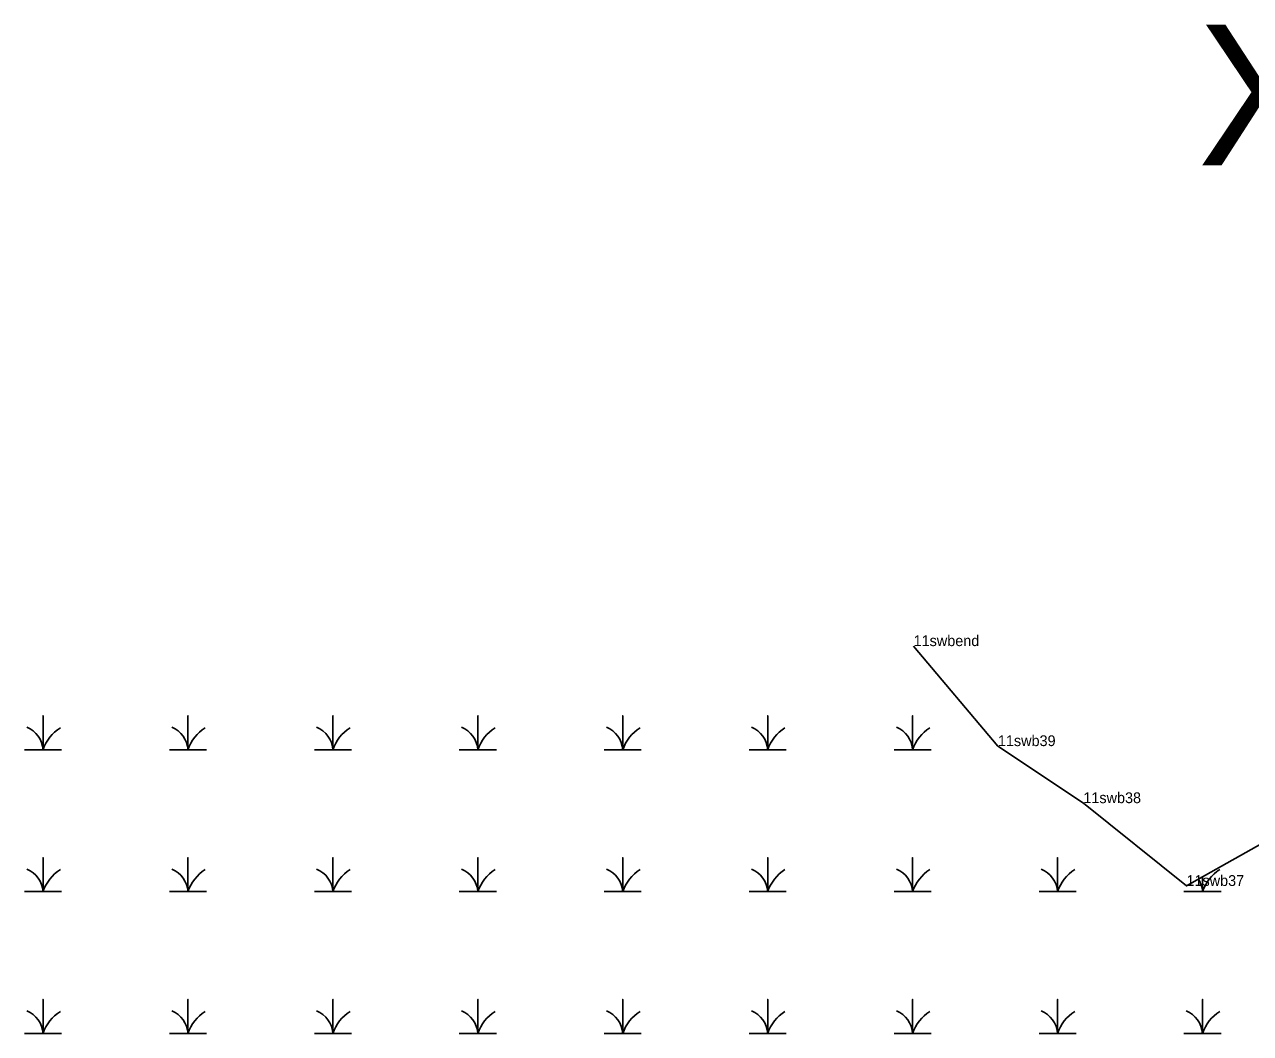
# Model space of a CAD drawing. Extents: x 2072529 to 2268796, y 436423 to 470406.
# Drawn here: x 2230006 to 2230575, y 447690 to 448159 of the extents above; entities that cross this region are included whole.
import ezdxf

# ---------------------------------------------------------------- set-up
doc = ezdxf.new("R2010")
doc.units = 0
for name, color, linetype in [('Default', 7, 'Continuous'), ('Exist Hydro Jurisdictional Stream or Body of Water NEU Mitigable', 7, 'Continuous'), ('Exist Hydro Jurisdictional Stream or Body of Water NEU Mitigable Cogo Comment', 7, 'Continuous'), ('Exist Hydro Swamp or Marsh', 7, 'Continuous'), ('Old_Level_20', 7, 'Continuous')]:
    doc.layers.add(name, color=color, linetype=linetype)

msp = doc.modelspace()

# ---------------------------------------------------------------- linework, layer by layer
at = {"layer": 'Exist Hydro Jurisdictional Stream or Body of Water NEU Mitigable'}
msp.add_lwpolyline([(2230418.67, 447870.17), (2230457.79, 447823.78), (2230497.45, 447797.32), (2230545.29, 447758.92), (2230589.1, 447783.55)], dxfattribs=at)
at = {"layer": 'Exist Hydro Swamp or Marsh'}
for points in [[(2230006.13, 447822.07), (2230014.73, 447822.07), (2230014.73, 447837.85), (2230014.73, 447822.07), (2230023.33, 447822.07)], [(2230073.38, 447822.07), (2230081.98, 447822.07), (2230081.98, 447837.85), (2230081.98, 447822.07), (2230090.58, 447822.07)], [(2230140.63, 447822.07), (2230149.23, 447822.07), (2230149.23, 447837.85), (2230149.23, 447822.07), (2230157.83, 447822.07)], [(2230207.88, 447822.07), (2230216.48, 447822.07), (2230216.48, 447837.85), (2230216.48, 447822.07), (2230225.08, 447822.07)], [(2230275.13, 447822.07), (2230283.73, 447822.07), (2230283.73, 447837.85), (2230283.73, 447822.07), (2230292.33, 447822.07)], [(2230342.38, 447822.07), (2230350.98, 447822.07), (2230350.98, 447837.85), (2230350.98, 447822.07), (2230359.58, 447822.07)], [(2230409.63, 447822.07), (2230418.23, 447822.07), (2230418.23, 447837.85), (2230418.23, 447822.07), (2230426.83, 447822.07)], [(2230006.13, 447756.27), (2230014.73, 447756.27), (2230014.73, 447772.05), (2230014.73, 447756.27), (2230023.33, 447756.27)], [(2230073.38, 447756.27), (2230081.98, 447756.27), (2230081.98, 447772.05), (2230081.98, 447756.27), (2230090.58, 447756.27)], [(2230140.63, 447756.27), (2230149.23, 447756.27), (2230149.23, 447772.05), (2230149.23, 447756.27), (2230157.83, 447756.27)], [(2230207.88, 447756.27), (2230216.48, 447756.27), (2230216.48, 447772.05), (2230216.48, 447756.27), (2230225.08, 447756.27)], [(2230275.13, 447756.27), (2230283.73, 447756.27), (2230283.73, 447772.05), (2230283.73, 447756.27), (2230292.33, 447756.27)], [(2230342.38, 447756.27), (2230350.98, 447756.27), (2230350.98, 447772.05), (2230350.98, 447756.27), (2230359.58, 447756.27)], [(2230409.63, 447756.27), (2230418.23, 447756.27), (2230418.23, 447772.05), (2230418.23, 447756.27), (2230426.83, 447756.27)], [(2230476.88, 447756.27), (2230485.48, 447756.27), (2230485.48, 447772.05), (2230485.48, 447756.27), (2230494.08, 447756.27)], [(2230544.13, 447756.27), (2230552.73, 447756.27), (2230552.73, 447763.11)], [(2230552.73, 447763.11), (2230552.73, 447756.27), (2230561.33, 447756.27)], [(2230006.13, 447690.47), (2230014.73, 447690.47), (2230014.73, 447706.25), (2230014.73, 447690.47), (2230023.33, 447690.47)], [(2230073.38, 447690.47), (2230081.98, 447690.47), (2230081.98, 447706.25), (2230081.98, 447690.47), (2230090.58, 447690.47)], [(2230140.63, 447690.47), (2230149.23, 447690.47), (2230149.23, 447706.25), (2230149.23, 447690.47), (2230157.83, 447690.47)], [(2230207.88, 447690.47), (2230216.48, 447690.47), (2230216.48, 447706.25), (2230216.48, 447690.47), (2230225.08, 447690.47)], [(2230275.13, 447690.47), (2230283.73, 447690.47), (2230283.73, 447706.25), (2230283.73, 447690.47), (2230292.33, 447690.47)], [(2230342.38, 447690.47), (2230350.98, 447690.47), (2230350.98, 447706.25), (2230350.98, 447690.47), (2230359.58, 447690.47)], [(2230409.63, 447690.47), (2230418.23, 447690.47), (2230418.23, 447706.25), (2230418.23, 447690.47), (2230426.83, 447690.47)], [(2230476.88, 447690.47), (2230485.48, 447690.47), (2230485.48, 447706.25), (2230485.48, 447690.47), (2230494.08, 447690.47)], [(2230544.13, 447690.47), (2230552.73, 447690.47), (2230552.73, 447706.25), (2230552.73, 447690.47), (2230561.33, 447690.47)]]:
    msp.add_lwpolyline(points, dxfattribs=at)
for centre, radius, start, end in [((2230002.47, 447821.19), 12.3, 4.1403, 67.535), ((2230032.97, 447816.01), 19.22, 122.1274, 161.6222), ((2230069.72, 447821.19), 12.3, 4.1403, 67.535), ((2230100.22, 447816.01), 19.22, 122.1274, 161.6222), ((2230136.97, 447821.19), 12.3, 4.1403, 67.535), ((2230167.47, 447816.01), 19.22, 122.1274, 161.6222), ((2230204.22, 447821.19), 12.3, 4.1403, 67.535), ((2230234.72, 447816.01), 19.22, 122.1274, 161.6222), ((2230271.47, 447821.19), 12.3, 4.1403, 67.535), ((2230301.97, 447816.01), 19.22, 122.1274, 161.6222), ((2230338.72, 447821.19), 12.3, 4.1403, 67.535), ((2230369.22, 447816.01), 19.22, 122.1274, 161.6222), ((2230405.97, 447821.19), 12.3, 4.1403, 67.535), ((2230436.47, 447816.01), 19.22, 122.1274, 161.6222), ((2230002.47, 447755.39), 12.3, 4.1403, 67.535), ((2230032.97, 447750.21), 19.22, 122.1274, 161.6222), ((2230069.72, 447755.39), 12.3, 4.1403, 67.535), ((2230100.22, 447750.21), 19.22, 122.1274, 161.6222), ((2230136.97, 447755.39), 12.3, 4.1403, 67.535), ((2230167.47, 447750.21), 19.22, 122.1274, 161.6222), ((2230204.22, 447755.39), 12.3, 4.1403, 67.535), ((2230234.72, 447750.21), 19.22, 122.1274, 161.6222), ((2230271.47, 447755.39), 12.3, 4.1403, 67.535), ((2230301.97, 447750.21), 19.22, 122.1274, 161.6222), ((2230338.72, 447755.39), 12.3, 4.1403, 67.535), ((2230369.22, 447750.21), 19.22, 122.1274, 161.6222), ((2230405.97, 447755.39), 12.3, 4.1403, 67.535), ((2230436.47, 447750.21), 19.22, 122.1274, 161.6222), ((2230473.22, 447755.39), 12.3, 4.1403, 67.535), ((2230503.72, 447750.21), 19.22, 122.1274, 161.6222), ((2230540.47, 447755.39), 12.3, 4.1403, 32.6931), ((2230570.97, 447750.21), 19.22, 122.1274, 161.6222), ((2230002.47, 447689.59), 12.3, 4.1403, 67.535), ((2230032.97, 447684.41), 19.22, 122.1274, 161.6222), ((2230069.72, 447689.59), 12.3, 4.1403, 67.535), ((2230100.22, 447684.41), 19.22, 122.1274, 161.6222), ((2230136.97, 447689.59), 12.3, 4.1403, 67.535), ((2230167.47, 447684.41), 19.22, 122.1274, 161.6222), ((2230204.22, 447689.59), 12.3, 4.1403, 67.535), ((2230234.72, 447684.41), 19.22, 122.1274, 161.6222), ((2230271.47, 447689.59), 12.3, 4.1403, 67.535), ((2230301.97, 447684.41), 19.22, 122.1274, 161.6222), ((2230338.72, 447689.59), 12.3, 4.1403, 67.535), ((2230369.22, 447684.41), 19.22, 122.1274, 161.6222), ((2230405.97, 447689.59), 12.3, 4.1403, 67.535), ((2230436.47, 447684.41), 19.22, 122.1274, 161.6222), ((2230473.22, 447689.59), 12.3, 4.1403, 67.535), ((2230503.72, 447684.41), 19.22, 122.1274, 161.6222), ((2230540.47, 447689.59), 12.3, 4.1403, 67.535), ((2230570.97, 447684.41), 19.22, 122.1274, 161.6222)]:
    msp.add_arc(centre, radius, start, end, dxfattribs=at)
at = {"layer": 'Old_Level_20'}
for p, q in [((2230418.67, 447870.17), (2230418.67, 447870.17)), ((2230457.79, 447823.78), (2230457.79, 447823.78)), ((2230497.45, 447797.32), (2230497.45, 447797.32)), ((2230545.29, 447758.92), (2230545.29, 447758.92))]:
    msp.add_line(p, q, dxfattribs=at)

# ---------------------------------------------------------------- texts
at = {"layer": 'Default'}
msp.add_text('XR', height=65.34, dxfattribs=at).set_placement((2230550.61, 448093.17))
at = {"layer": 'Exist Hydro Jurisdictional Stream or Body of Water NEU Mitigable Cogo Comment'}
for s, p in [('11swbend', (2230418.67, 447870.17)), ('11swb39', (2230457.79, 447823.78)), ('11swb38', (2230497.45, 447797.32)), ('11swb37', (2230545.29, 447758.92))]:
    msp.add_text(s, height=5, dxfattribs=at).set_placement(p)

doc.saveas('drawing.dxf')
